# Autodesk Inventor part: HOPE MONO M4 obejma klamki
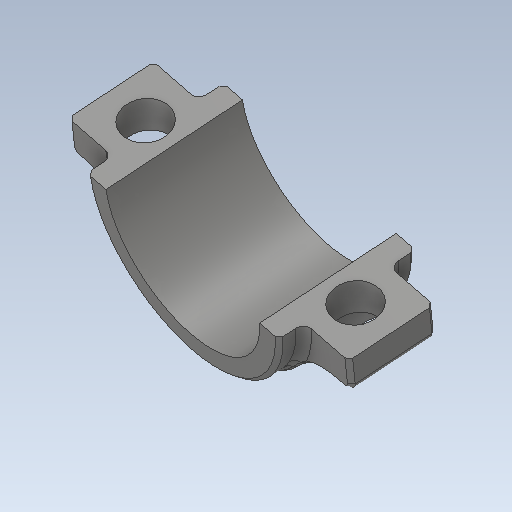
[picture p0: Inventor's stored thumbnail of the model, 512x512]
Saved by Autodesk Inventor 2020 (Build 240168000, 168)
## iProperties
Created: 2015-11
Part Number: HOPE MONO M4 obejma klamki
Material: Ogólny
Document SubType Name: Modeling
Designer: Tomasz
Density: 1 g/cm^3
Appearance: Domyślna
Sending System: SolidWorks 2017
Last Author: Tomasz
Last Saved: 2017-11-19
Author: Tomasz
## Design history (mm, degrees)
feature "Imported1"
node "Bryła1"
